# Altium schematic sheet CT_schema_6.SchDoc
size 287 x 160 mm
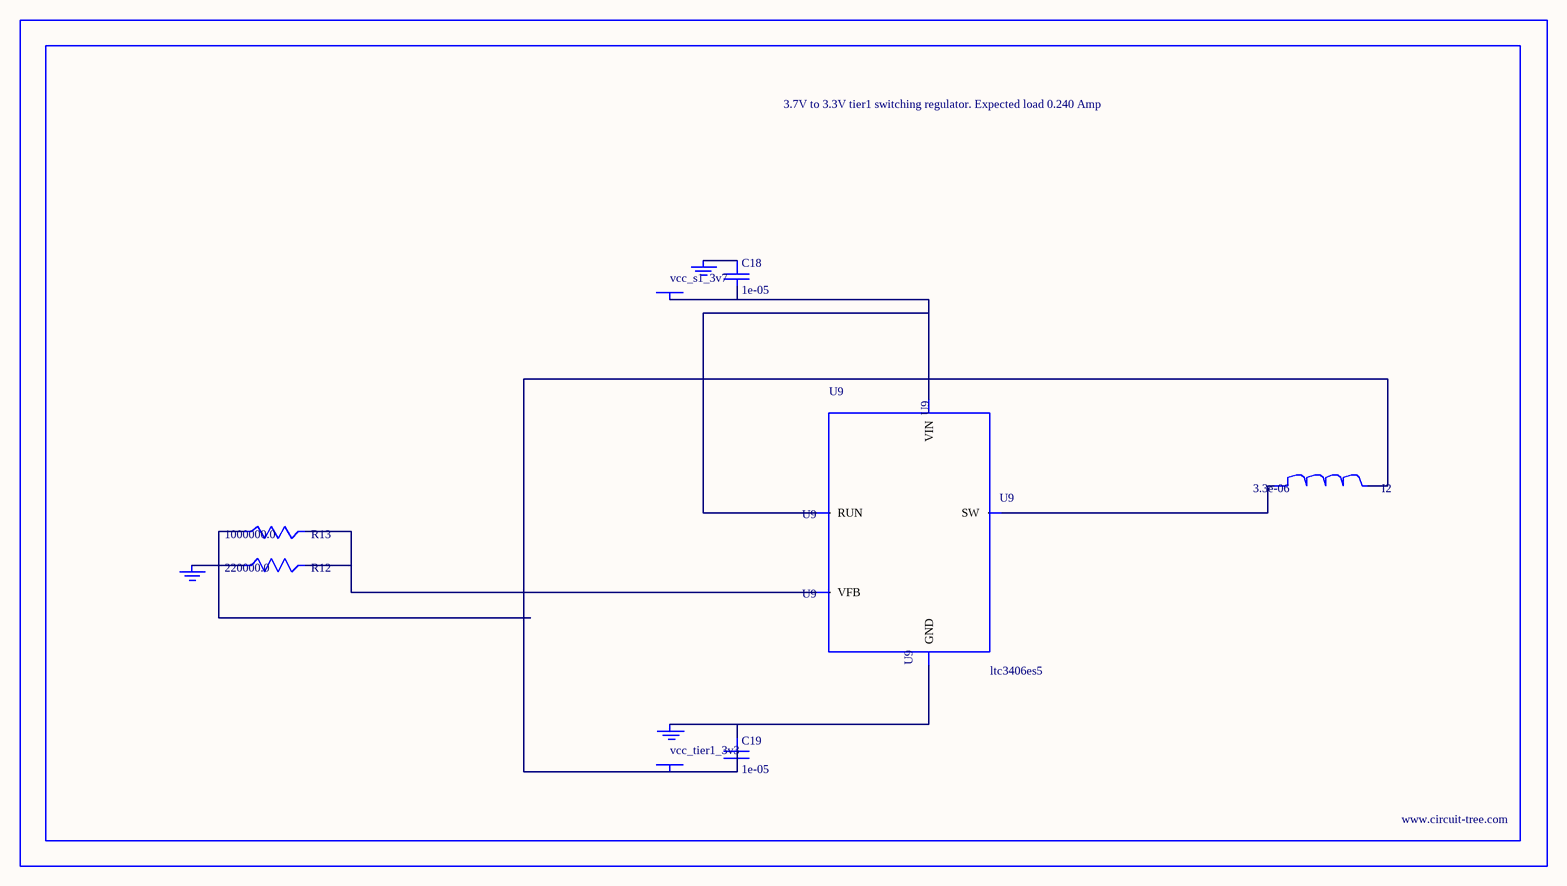
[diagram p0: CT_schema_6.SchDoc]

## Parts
BORDER5  (no value)
C18  1e-05  [C0805]
C19  1e-05  [C0805]
GND_INSTANCE_5_0  (no value)
GND_INSTANCE_5_1  (no value)
GND_INSTANCE_5_2  (no value)
I2  3.3e-06  [L0806]
POWER_INSTANCE_5_0  vcc_tier1_3v3
POWER_INSTANCE_5_1  vcc_s1_3v7
R12  220000.0  [R0603]
R13  1000000.0  [R0603]
U9  ltc3406es5  [TSOT-23-5]

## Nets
NetC18_1: C18.1 GND_INSTANCE_5_1.0(GND)
NetC18_2: C18.2 POWER_INSTANCE_5_1.0(PWR) U9.1(RUN) U9.4(VIN)
NetC19_1: C19.1 GND_INSTANCE_5_0.0(GND) U9.2(GND)
NetC19_2: C19.2 I2.2 POWER_INSTANCE_5_0.0(PWR) R13.1
NetGND_INSTANCE_5_2_0: GND_INSTANCE_5_2.0(GND) R12.1
NetI2_1: I2.1 U9.3(SW)
NetR12_2: R12.2 R13.2 U9.5(VFB)

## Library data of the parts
BORDER5 = BORDER_PAGE5
C18 C19 = C0805C106K8RACTU
GND_INSTANCE_5_0-GND_INSTANCE_5_2 = GND
I2 = L0806C3R3MDWIT
POWER_INSTANCE_5_0 POWER_INSTANCE_5_1 = PWR
R12 = RC0603JR-07220KL
R13 = RC0603JR-071ML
